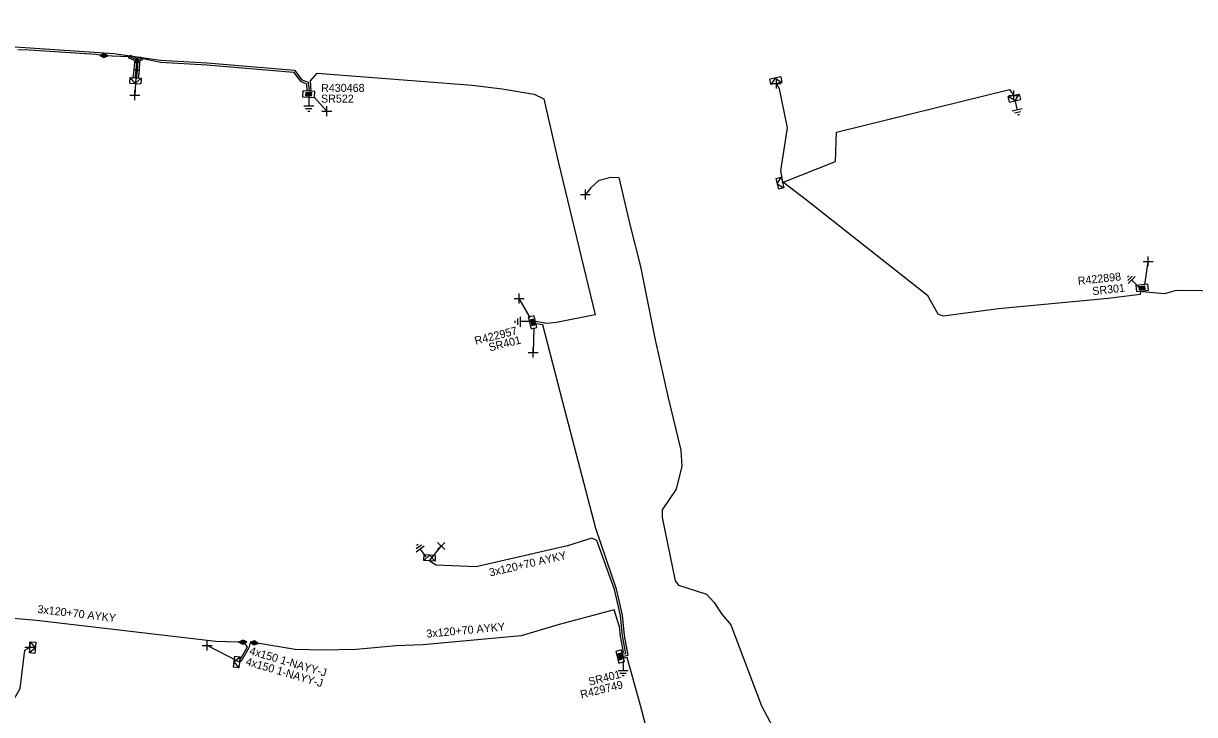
# Model space of a CAD drawing. Extents: x -540466 to -537383, y -1184038 to -1179972.
# Drawn here: x -537854 to -537707.7, y -1180709.3 to -1180623 of the extents above; entities that cross this region are included whole.
import ezdxf

# ---------------------------------------------------------------- set-up
doc = ezdxf.new("R2010")
doc.units = 0
for name, color, linetype in [('Vrstva 1', 7, 'Continuous'), ('Vrstva 14', 7, 'Continuous'), ('Vrstva 15', 7, 'Continuous'), ('Vrstva 19', 7, 'Continuous'), ('Vrstva 20', 7, 'Continuous'), ('Vrstva 28', 7, 'Continuous'), ('Vrstva 29', 7, 'Continuous'), ('Vrstva 30', 7, 'Continuous'), ('Vrstva 31', 7, 'Continuous'), ('Vrstva 34', 7, 'Continuous'), ('Vrstva 4', 7, 'Continuous'), ('Vrstva 5', 7, 'Continuous'), ('Vrstva 52', 7, 'Continuous'), ('Vrstva 59', 7, 'Continuous'), ('Vrstva 6', 7, 'Continuous'), ('Vrstva 8', 7, 'Continuous'), ('Vrstva 9', 7, 'Continuous')]:
    doc.layers.add(name, color=color, linetype=linetype)

# ---------------------------------------------------------------- blocks, each defined once
blk = doc.blocks.new('NN870')
at = {"layer": 'Vrstva 4'}
for points in [[(0, -0.25), (0.5, 0), (0, 0.25), (-0.5, 0), (0, -0.25)], [(0.37, 0), (0, 0.19), (-0.36, 0), (0, -0.19), (0.37, 0)], [(0.24, 0), (0, 0.12), (-0.25, 0), (0, -0.12), (0.24, 0)], [(0.12, 0), (0, 0.06), (-0.13, 0), (0, -0.06), (0.12, 0)]]:
    blk.add_lwpolyline(points, dxfattribs=at)
blk = doc.blocks.new('NN800')
at = {"layer": 'Vrstva 1'}
for points in [[(-0.44, 0.44), (0.44, -0.44)], [(-0.44, -0.44), (0.44, 0.44)]]:
    blk.add_lwpolyline(points, dxfattribs=at)
blk = doc.blocks.new('NN620')
at = {"layer": 'Vrstva 8'}
for points in [[(0.75, 0), (-0.75, 0)], [(-0.75, 0), (-0.75, -0.75)], [(0.75, -0.75), (0.75, 0)], [(-0.75, -0.75), (0.75, -0.75)], [(0.37, -0.18), (-0.38, -0.18)], [(-0.38, -0.18), (-0.38, -0.56)], [(-0.38, -0.56), (0.37, -0.56)], [(0.32, -0.23), (-0.33, -0.23)], [(-0.33, -0.23), (-0.33, -0.51)], [(-0.33, -0.51), (0.32, -0.51)], [(0.27, -0.27), (-0.28, -0.27)], [(-0.28, -0.27), (-0.28, -0.46)], [(-0.28, -0.46), (0.27, -0.46)], [(0.23, -0.32), (-0.23, -0.32)], [(-0.23, -0.32), (-0.23, -0.42)], [(-0.23, -0.42), (0.23, -0.42)], [(-0.19, -0.37), (0.19, -0.37)], [(0.23, -0.42), (0.23, -0.32)], [(0.27, -0.46), (0.27, -0.27)], [(0.32, -0.51), (0.32, -0.23)], [(0.37, -0.56), (0.37, -0.18)]]:
    blk.add_lwpolyline(points, dxfattribs=at)
blk = doc.blocks.new('NN630')
at = {"layer": 'Vrstva 9'}
for points in [[(0, -0.7), (-0.7, 0)], [(-0.7, -0.7), (-0.7, 0), (0.7, 0), (0.7, -0.7)], [(-0.7, -0.7), (0.7, -0.7)], [(0, -0.7), (0.7, 0)]]:
    blk.add_lwpolyline(points, dxfattribs=at)
blk = doc.blocks.new('NN810')
at = {"layer": 'Vrstva 14'}
for points in [[(0, -0.64), (0, -1.89)], [(0.63, -1.89), (-0.62, -1.89)], [(0.39, -2.2), (-0.4, -2.2)], [(0, -2.52), (-0.12, -2.52)], [(0.14, -2.52), (0, -2.52)]]:
    blk.add_lwpolyline(points, dxfattribs=at)

msp = doc.modelspace()

# ---------------------------------------------------------------- linework, layer by layer
at = {"layer": 'Vrstva 20'}
for points in [[(-537840.67, -1180627), (-537840.01, -1180627.26), (-537839.61, -1180627.72), (-537839.91, -1180627.98), (-537840.25, -1180627.6), (-537840.81, -1180627.38)], [(-537840.13, -1180628.84), (-537840.06, -1180627.83), (-537839.46, -1180627.87), (-537839.53, -1180628.88)], [(-537839.15, -1180627.57), (-537839.42, -1180627.7), (-537839.59, -1180627.96), (-537839.93, -1180627.74), (-537839.68, -1180627.38), (-537839.31, -1180627.21)], [(-537840.25, -1180629.8), (-537840.13, -1180628.82), (-537839.53, -1180628.9), (-537839.65, -1180629.88)]]:
    msp.add_lwpolyline(points, close=True, dxfattribs=at)
at = {"layer": 'Vrstva 5'}
for points in [[(-537909.31, -1180691.06), (-537909.75, -1180690.63), (-537910.51, -1180689.86), (-537910.64, -1180688.94), (-537908.88, -1180682.44), (-537907.61, -1180677.05), (-537907.55, -1180674.95), (-537903.95, -1180656.66), (-537901.81, -1180645.14), (-537898.14, -1180625.27), (-537897.51, -1180623.62), (-537897.15, -1180623.19), (-537894.65, -1180623.04), (-537887.06, -1180623.47), (-537879.68, -1180624.11), (-537871.16, -1180624.78), (-537859.96, -1180625.61), (-537842.69, -1180626.79), (-537836.84, -1180627.63), (-537831.04, -1180627.98), (-537820.1, -1180628.88), (-537819.2, -1180630.08), (-537818.39, -1180630.39), (-537818.28, -1180631.48)], [(-537854.69, -1180626.3), (-537853.24, -1180626.32), (-537844.92, -1180626.88), (-537843.93, -1180627.05)], [(-537843.93, -1180627.05), (-537840.74, -1180627.19), (-537840.13, -1180627.43), (-537839.85, -1180627.74), (-537839.92, -1180628.86), (-537840.02, -1180629.63), (-537839.95, -1180629.84)], [(-537839.95, -1180629.84), (-537839.82, -1180629.65), (-537839.72, -1180628.87), (-537839.65, -1180627.69), (-537839.55, -1180627.54), (-537839.23, -1180627.39), (-537836.86, -1180627.87), (-537831.06, -1180628.23), (-537820.24, -1180629.12), (-537819.38, -1180630.27), (-537818.62, -1180630.58), (-537818.56, -1180631.46)], [(-537818.04, -1180631.5), (-537818.12, -1180630.22), (-537817.28, -1180629.26), (-537797.92, -1180630.76), (-537794.16, -1180631.22), (-537790.18, -1180631.86), (-537788.96, -1180632.47), (-537787.17, -1180640.3), (-537782.56, -1180659.43), (-537787.39, -1180660.39), (-537788.61, -1180660.5), (-537789.99, -1180660.28)], [(-537783.09, -1180643.59), (-537782.07, -1180642.62), (-537780.61, -1180642.22), (-537779.58, -1180642.27), (-537778.18, -1180648.3), (-537776.88, -1180653.38), (-537775.06, -1180662.55), (-537773.45, -1180669.78), (-537771.84, -1180676.34), (-537771.71, -1180678.32), (-537772.45, -1180681.2), (-537774.2, -1180683.78), (-537774.17, -1180684.72), (-537772.56, -1180692.63), (-537772.13, -1180693.2), (-537768.63, -1180694.32), (-537767.68, -1180695.35), (-537766.74, -1180696.81), (-537765.6, -1180698.14), (-537761.76, -1180708.24), (-537758.24, -1180714.9)], [(-537714.45, -1180656.49), (-537714.46, -1180656.89), (-537718.48, -1180657.39), (-537732.15, -1180658.69), (-537739.1, -1180659.6), (-537739.7, -1180659.35), (-537741, -1180657.05), (-537756.17, -1180645.11), (-537758.98, -1180642.94), (-537759.15, -1180642.9)], [(-537655.89, -1180710.2), (-537658.59, -1180707.01), (-537663.98, -1180698.82), (-537667.6, -1180696.73), (-537670.58, -1180694.42), (-537673.47, -1180694.14), (-537675.09, -1180692.79), (-537678.56, -1180687.36), (-537679.5, -1180684.49), (-537679.62, -1180682.84), (-537680.35, -1180681.01), (-537682.22, -1180679.41), (-537684.65, -1180675.6), (-537692.7, -1180662.05), (-537695.95, -1180659.82), (-537700.51, -1180657.04), (-537703.47, -1180656.49), (-537706.77, -1180656.42), (-537709.99, -1180656.4), (-537711.42, -1180656.82), (-537714.2, -1180656.56), (-537714.2, -1180656.46)], [(-537779.03, -1180702.05), (-537778.45, -1180701.94), (-537778.9, -1180699.46), (-537779.15, -1180696.92), (-537779.88, -1180693.68), (-537782.47, -1180686.13), (-537786.58, -1180670.35), (-537789.1, -1180660.67), (-537789.92, -1180660.55)], [(-537826.57, -1180700.29), (-537827.18, -1180700.3), (-537829.92, -1180700.24), (-537852.35, -1180697.59), (-537852.79, -1180697.56), (-537860.57, -1180696.88), (-537862.47, -1180696.57), (-537861.67, -1180687.9), (-537861.38, -1180685.83)], [(-537779.09, -1180701.81), (-537778.71, -1180701.74), (-537779.15, -1180699.51), (-537779.39, -1180696.96), (-537780.12, -1180693.74), (-537782.34, -1180687.61), (-537782.99, -1180687.31), (-537786, -1180688.26), (-537797.4, -1180690.89), (-537802.41, -1180690.69), (-537802.93, -1180690.38), (-537803.26, -1180690.15)], [(-537779.15, -1180701.57), (-537779, -1180701.54), (-537779.4, -1180699.55), (-537779.5, -1180698.39), (-537780.16, -1180696.25), (-537787.04, -1180698.11), (-537791.79, -1180699.52), (-537804.08, -1180700.65), (-537807.4, -1180700.78), (-537812.42, -1180701.23), (-537816.61, -1180701.32), (-537820.02, -1180701.24), (-537824.76, -1180700.45), (-537825.15, -1180700.38)], [(-537825.15, -1180700.38), (-537825.68, -1180700.51), (-537825.83, -1180701.03), (-537826.78, -1180702.66), (-537826.99, -1180702.82), (-537826.96, -1180702.56), (-537825.98, -1180700.89), (-537826.13, -1180700.68), (-537826.57, -1180700.29)], [(-537767.23, -1180739.35), (-537770.39, -1180732.71), (-537771.75, -1180728.35), (-537772.33, -1180728.21), (-537771.79, -1180728.11), (-537773.73, -1180720.25), (-537776.91, -1180708.2), (-537778.57, -1180702.22), (-537778.97, -1180702.3)]]:
    msp.add_lwpolyline(points, dxfattribs=at)
at = {"layer": 'Vrstva 52'}
for points in [[(-537759.15, -1180642.9), (-537759.13, -1180642.81), (-537759.34, -1180641.45), (-537758.53, -1180636.07), (-537759.53, -1180631.21), (-537759.92, -1180630.54)], [(-537867.01, -1180711.14), (-537864.28, -1180712.85), (-537862.67, -1180713.6), (-537860.35, -1180714.7), (-537859.77, -1180713.84), (-537859.08, -1180711.89), (-537858.21, -1180709.98), (-537857.45, -1180709.34), (-537855.5, -1180708.05), (-537854.39, -1180706.1), (-537853.81, -1180701.3), (-537853.21, -1180700.99), (-537853.16, -1180700.95)]]:
    msp.add_lwpolyline(points, dxfattribs=at)
at = {"layer": 'Vrstva 59'}
for points in [[(-537839.95, -1180629.84), (-537840.06, -1180632)], [(-537817.66, -1180632.25), (-537816.09, -1180634.01)], [(-537759.15, -1180642.9), (-537752.53, -1180640.3), (-537752.42, -1180636.63), (-537730.81, -1180631.28), (-537730.27, -1180632.02)], [(-537783.09, -1180643.59), (-537783.78, -1180644.39)], [(-537713.9, -1180655.68), (-537713.49, -1180652.75)], [(-537790.68, -1180659.75), (-537792.03, -1180657.39)], [(-537790.21, -1180661.05), (-537790.31, -1180664.12)], [(-537803.26, -1180690.15), (-537801.79, -1180688.31)], [(-537826.99, -1180702.82), (-537831.01, -1180700.73)]]:
    msp.add_lwpolyline(points, dxfattribs=at)

# ---------------------------------------------------------------- block references
at = {"layer": 'Vrstva 15'}
for p in [(-537818.32, -1180631.5), (-537779.07, -1180702.01)]:
    msp.add_blockref('NN810', p, dxfattribs=at)
for p, rotation in [((-537730.27, -1180632.02), 13.178672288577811), ((-537714.19, -1180656.43), -135.2424277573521), ((-537790.01, -1180660.28), -90), ((-537803.26, -1180690.15), -143.0495916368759)]:
    msp.add_blockref('NN810', p, dxfattribs=dict(at, rotation=rotation))
at = {"layer": 'Vrstva 19'}
for p, rotation in [((-537843.93, -1180627.05), -2.5129359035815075), ((-537826.57, -1180700.29), -179.06080897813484), ((-537825.15, -1180700.38), -10.17551077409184)]:
    msp.add_blockref('NN870', p, dxfattribs=dict(at, rotation=rotation))
at = {"layer": 'Vrstva 28'}
for p, rotation in [((-537818.32, -1180631.5), -4.546858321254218), ((-537714.19, -1180656.43), -173.77038606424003), ((-537790.01, -1180660.28), -75.89639448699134), ((-537779.07, -1180702), -75.89639448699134)]:
    msp.add_blockref('NN620', p, dxfattribs=dict(at, rotation=rotation))
at = {"layer": 'Vrstva 31'}
for p, rotation in [((-537759.92, -1180630.54), -168.23326667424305), ((-537839.95, -1180629.84), -4.348538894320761), ((-537730.26, -1180632.02), 13.178672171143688), ((-537759.15, -1180642.9), -76.32872222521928), ((-537803.26, -1180690.15), 177.5015768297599), ((-537853.15, -1180700.95), 84.30260002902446), ((-537826.99, -1180702.82), -95.7874176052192)]:
    msp.add_blockref('NN630', p, dxfattribs=dict(at, rotation=rotation))
at = {"layer": 'Vrstva 34', "rotation": 45}
for p in [(-537759.92, -1180630.54), (-537840.06, -1180632), (-537730.27, -1180632.02), (-537816.09, -1180634.01), (-537783.78, -1180644.39), (-537713.49, -1180652.75), (-537792.03, -1180657.39), (-537790.31, -1180664.12), (-537853.16, -1180700.95), (-537831.01, -1180700.73)]:
    msp.add_blockref('NN800', p, dxfattribs=at)
at = {"layer": 'Vrstva 34'}
msp.add_blockref('NN800', (-537801.79, -1180688.31), dxfattribs=at)

# ---------------------------------------------------------------- texts
at = {"layer": 'Vrstva 29'}
msp.add_text('R430468', height=1, dxfattribs=at).set_placement((-537816.79, -1180631.59))
for s, rotation, p in [('R422898', 6.23, (-537722.21, -1180655.7)), ('R422957', 14.104, (-537797.47, -1180663.17)), ('R429749', 14.104, (-537784.27, -1180707.36))]:
    msp.add_text(s, height=1, rotation=rotation, dxfattribs=at).set_placement(p)
at = {"layer": 'Vrstva 30'}
msp.add_text('SR522', height=1, dxfattribs=at).set_placement((-537816.8, -1180632.93))
for s, rotation, p in [('SR301', 6.23, (-537720.4, -1180656.97)), ('SR401', 14.104, (-537795.71, -1180664)), ('SR401', 14.104, (-537783.26, -1180705.75))]:
    msp.add_text(s, height=1, rotation=rotation, dxfattribs=at).set_placement(p)
at = {"layer": 'Vrstva 6'}
for s, rotation, p in [('3x120+70 AYKY', 12.975, (-537795.67, -1180692.11)), ('3x120+70 AYKY', 353.266, (-537852.26, -1180696.65)), ('3x120+70 AYKY', 5.253, (-537803.59, -1180699.75)), ('4x150 1-NAYY-J', 343.503, (-537825.82, -1180701.81)), ('4x150 1-NAYY-J', 343.503, (-537826.28, -1180703.13))]:
    msp.add_text(s, height=1, rotation=rotation, dxfattribs=at).set_placement(p)

doc.saveas('drawing.dxf')
